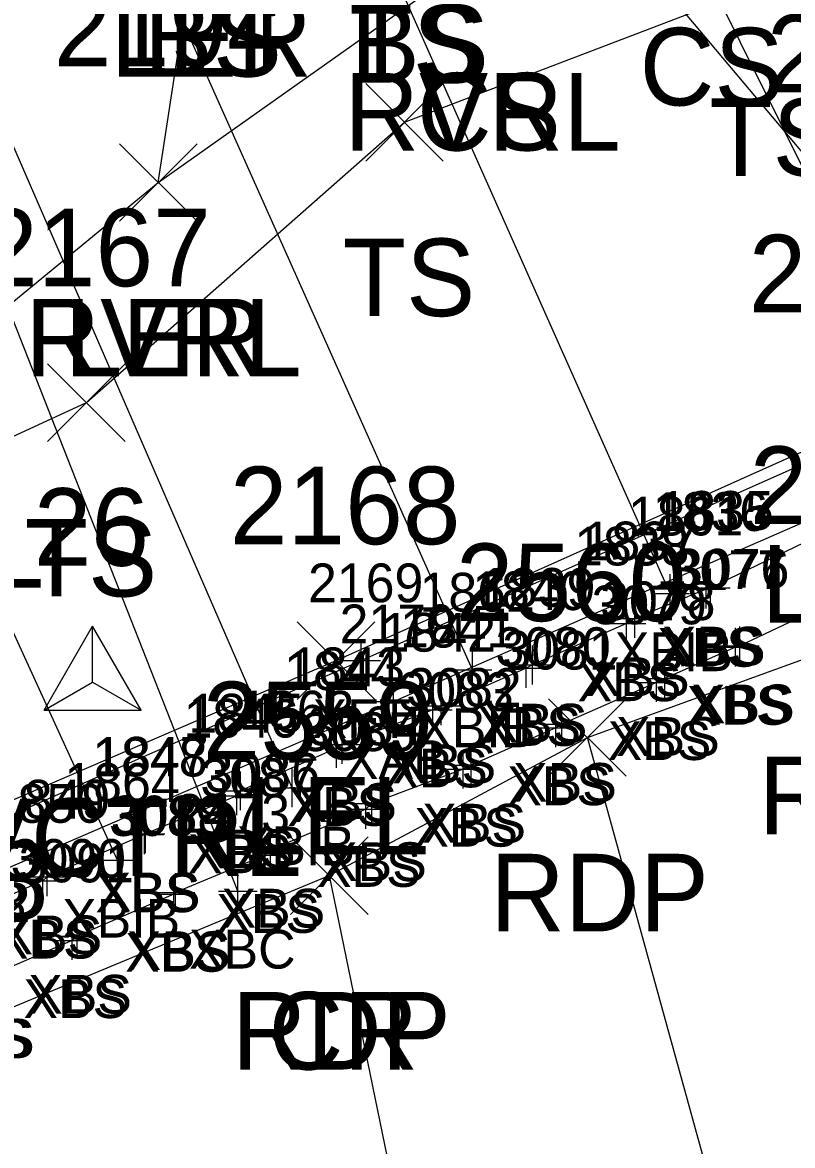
# Model space of a CAD drawing. Extents: x 1504228 to 1506103, y 437717 to 440106.
# Drawn here: x 1505221.56 to 1505241.43, y 438136.49 to 438165.45 of the extents above; entities that cross this region are included whole.
import ezdxf

# ---------------------------------------------------------------- set-up
doc = ezdxf.new("R2010")
doc.units = 0
for name, color, linetype in [('B_A', 7, 'Continuous'), ('B_I', 7, 'Continuous'), ('B_TIC', 7, 'Continuous'), ('BB', 7, 'Continuous'), ('BELB', 7, 'Continuous'), ('BFT', 7, 'Continuous'), ('BSE', 7, 'Continuous'), ('BSUBM', 7, 'Continuous'), ('C_A', 7, 'Continuous'), ('C_I', 7, 'Continuous'), ('CPSM', 7, 'Continuous'), ('L_A', 7, 'Continuous'), ('L_I', 7, 'Continuous'), ('L_TIC', 7, 'Continuous'), ('LARO', 7, 'Continuous'), ('LAWE', 7, 'Continuous'), ('LELB', 7, 'Continuous'), ('P_A', 7, 'Continuous'), ('P_I', 7, 'Continuous'), ('P_TIC', 7, 'Continuous'), ('PET', 7, 'Continuous'), ('PRC', 7, 'Continuous')]:
    doc.layers.add(name, color=color, linetype=linetype)

msp = doc.modelspace()

# ---------------------------------------------------------------- linework, layer by layer
at = {"layer": 'B_TIC'}
for p, q in [((1505238.275, 438150.725), (1505238.351, 438150.725)), ((1505239.203, 438150.84), (1505239.279, 438150.84)), ((1505239.321, 438150.871), (1505239.397, 438150.871)), ((1505237.363, 438150.082), (1505237.438, 438150.082)), ((1505237.147, 438149.952), (1505237.223, 438149.952)), ((1505239.962, 438149.343), (1505240.038, 438149.343)), ((1505240.074, 438149.38), (1505240.149, 438149.38)), ((1505230.306, 438149.002), (1505230.382, 438149.002)), ((1505233.18, 438148.763), (1505233.255, 438148.763)), ((1505234.558, 438148.799), (1505234.634, 438148.799)), ((1505234.723, 438148.885), (1505234.799, 438148.885)), ((1505237.922, 438148.434), (1505237.997, 438148.434)), ((1505238.14, 438148.54), (1505238.216, 438148.54)), ((1505231.138, 438147.944), (1505231.213, 438147.944)), ((1505232.371, 438147.836), (1505232.446, 438147.836)), ((1505232.155, 438147.729), (1505232.23, 438147.729)), ((1505235.331, 438147.268), (1505235.406, 438147.268)), ((1505235.483, 438147.357), (1505235.559, 438147.357)), ((1505229.663, 438146.737), (1505229.739, 438146.737)), ((1505229.809, 438146.837), (1505229.885, 438146.837)), ((1505233.14, 438146.305), (1505233.215, 438146.305)), ((1505232.933, 438146.201), (1505233.008, 438146.201)), ((1505228.526, 438145.721), (1505228.601, 438145.721)), ((1505227.095, 438145.514), (1505227.17, 438145.514)), ((1505227.192, 438145.642), (1505227.268, 438145.642)), ((1505230.422, 438145.164), (1505230.497, 438145.164)), ((1505230.581, 438145.312), (1505230.656, 438145.312)), ((1505224.712, 438144.511), (1505224.788, 438144.511)), ((1505224.739, 438144.531), (1505224.815, 438144.531)), ((1505227.824, 438143.977), (1505227.899, 438143.977)), ((1505227.96, 438144.114), (1505228.036, 438144.114)), ((1505224.017, 438143.855), (1505224.093, 438143.855)), ((1505222.205, 438143.424), (1505222.281, 438143.424)), ((1505222.086, 438143.316), (1505222.162, 438143.316)), ((1505225.471, 438142.975), (1505225.547, 438142.975)), ((1505225.514, 438143.016), (1505225.59, 438143.016)), ((1505227.125, 438143.057), (1505227.2, 438143.057)), ((1505222.849, 438141.78), (1505222.924, 438141.78)), ((1505222.972, 438141.895), (1505223.047, 438141.895))]:
    msp.add_line(p, q, dxfattribs=at)
for points in [[(1505238.272, 438150.225), (1505238.272, 438151.225)], [(1505239.2, 438150.34), (1505239.2, 438151.34)], [(1505239.318, 438150.371), (1505239.318, 438151.371)], [(1505237.772, 438150.725), (1505238.772, 438150.725)], [(1505238.7, 438150.84), (1505239.7, 438150.84)], [(1505238.818, 438150.871), (1505239.818, 438150.871)], [(1505237.144, 438149.452), (1505237.144, 438150.452)], [(1505237.359, 438149.582), (1505237.359, 438150.582)], [(1505236.859, 438150.082), (1505237.859, 438150.082)], [(1505236.644, 438149.952), (1505237.644, 438149.952)], [(1505239.959, 438148.843), (1505239.959, 438149.843)], [(1505240.07, 438148.88), (1505240.07, 438149.88)], [(1505230.303, 438148.502), (1505230.303, 438149.502)], [(1505233.176, 438148.263), (1505233.176, 438149.263)], [(1505234.555, 438148.299), (1505234.555, 438149.299)], [(1505234.72, 438148.385), (1505234.72, 438149.385)], [(1505239.459, 438149.343), (1505240.459, 438149.343)], [(1505239.57, 438149.38), (1505240.57, 438149.38)], [(1505229.803, 438149.002), (1505230.803, 438149.002)], [(1505237.918, 438147.934), (1505237.918, 438148.934)], [(1505238.137, 438148.04), (1505238.137, 438149.04)], [(1505232.676, 438148.763), (1505233.676, 438148.763)], [(1505234.055, 438148.799), (1505235.055, 438148.799)], [(1505234.22, 438148.885), (1505235.22, 438148.885)], [(1505231.134, 438147.444), (1505231.134, 438148.444)], [(1505232.367, 438147.336), (1505232.367, 438148.336)], [(1505237.418, 438148.434), (1505238.418, 438148.434)], [(1505237.637, 438148.54), (1505238.637, 438148.54)], [(1505232.151, 438147.229), (1505232.151, 438148.229)], [(1505230.634, 438147.944), (1505231.634, 438147.944)], [(1505231.867, 438147.836), (1505232.867, 438147.836)], [(1505235.327, 438146.768), (1505235.327, 438147.768)], [(1505235.48, 438146.857), (1505235.48, 438147.857)], [(1505231.651, 438147.729), (1505232.651, 438147.729)], [(1505229.66, 438146.237), (1505229.66, 438147.237)], [(1505229.806, 438146.337), (1505229.806, 438147.337)], [(1505234.827, 438147.268), (1505235.827, 438147.268)], [(1505234.98, 438147.357), (1505235.98, 438147.357)], [(1505229.16, 438146.737), (1505230.16, 438146.737)], [(1505229.306, 438146.837), (1505230.306, 438146.837)], [(1505232.929, 438145.701), (1505232.929, 438146.701)], [(1505233.136, 438145.805), (1505233.136, 438146.805)], [(1505232.636, 438146.305), (1505233.636, 438146.305)], [(1505227.091, 438145.014), (1505227.091, 438146.014)], [(1505227.189, 438145.142), (1505227.189, 438146.142)], [(1505228.522, 438145.221), (1505228.522, 438146.221)], [(1505232.429, 438146.201), (1505233.429, 438146.201)], [(1505228.022, 438145.721), (1505229.022, 438145.721)], [(1505230.577, 438144.812), (1505230.577, 438145.812)], [(1505226.591, 438145.514), (1505227.591, 438145.514)], [(1505226.689, 438145.642), (1505227.689, 438145.642)], [(1505230.418, 438144.664), (1505230.418, 438145.664)], [(1505229.918, 438145.164), (1505230.918, 438145.164)], [(1505230.077, 438145.312), (1505231.077, 438145.312)], [(1505224.709, 438144.011), (1505224.709, 438145.011)], [(1505224.736, 438144.031), (1505224.736, 438145.031)], [(1505227.957, 438143.614), (1505227.957, 438144.614)], [(1505224.014, 438143.355), (1505224.014, 438144.355)], [(1505224.209, 438144.511), (1505225.209, 438144.511)], [(1505224.236, 438144.531), (1505225.236, 438144.531)], [(1505227.82, 438143.477), (1505227.82, 438144.477)], [(1505227.32, 438143.977), (1505228.32, 438143.977)], [(1505227.457, 438144.114), (1505228.457, 438144.114)], [(1505222.083, 438142.816), (1505222.083, 438143.816)], [(1505222.202, 438142.924), (1505222.202, 438143.924)], [(1505223.514, 438143.855), (1505224.514, 438143.855)], [(1505221.702, 438143.424), (1505222.702, 438143.424)], [(1505225.468, 438142.475), (1505225.468, 438143.475)], [(1505225.511, 438142.516), (1505225.511, 438143.516)], [(1505227.121, 438142.557), (1505227.121, 438143.557)], [(1505221.583, 438143.316), (1505222.583, 438143.316)], [(1505224.968, 438142.975), (1505225.968, 438142.975)], [(1505225.011, 438143.016), (1505226.011, 438143.016)], [(1505226.621, 438143.057), (1505227.621, 438143.057)], [(1505222.846, 438141.28), (1505222.846, 438142.28)], [(1505222.968, 438141.395), (1505222.968, 438142.395)], [(1505222.346, 438141.78), (1505223.346, 438141.78)], [(1505222.468, 438141.895), (1505223.468, 438141.895)]]:
    msp.add_lwpolyline(points, dxfattribs=at)
at = {"layer": 'BB'}
for points in [[(1505245.599, 438153.876), (1505225.746, 438193.733)], [(1505238.272, 438150.725), (1505220.207, 438191.242)], [(1505233.176, 438148.763), (1505215.135, 438189.07)], [(1505228.522, 438145.721), (1505210.599, 438186.937)], [(1505224.014, 438143.855), (1505205.318, 438184.714)]]:
    msp.add_lwpolyline(points, dxfattribs=at)
at = {"layer": 'BELB'}
for points in [[(1505189.093, 438232.07), (1505202.074, 438213.317), (1505217.089, 438192.519), (1505234.002, 438171.224), (1505249.231, 438153.134)], [(1505227.121, 438143.057), (1505216.699, 438169.498), (1505208.631, 438188.54), (1505199.093, 438209.718)]]:
    msp.add_lwpolyline(points, dxfattribs=at)
at = {"layer": 'BFT'}
msp.add_lwpolyline([(1505211.711, 438138.978), (1505211.593, 438140.8), (1505215.376, 438142.417), (1505230.303, 438149.002), (1505243.278, 438154.766), (1505246.019, 438155.885), (1505263.291, 438163.511), (1505271.064, 438167.183), (1505276.649, 438169.866), (1505288.201, 438174.699), (1505288.73, 438173.49)], dxfattribs=at)
at = {"layer": 'BSE'}
for points in [[(1505242.683, 438152.495), (1505239.318, 438150.871), (1505239.2, 438150.84), (1505237.359, 438150.082), (1505237.144, 438149.952), (1505234.72, 438148.885), (1505234.555, 438148.799), (1505232.367, 438147.836), (1505232.151, 438147.729), (1505229.806, 438146.837), (1505229.66, 438146.737), (1505227.189, 438145.642), (1505227.091, 438145.514), (1505224.736, 438144.531), (1505224.709, 438144.511), (1505222.202, 438143.424), (1505222.083, 438143.316), (1505219.691, 438142.273), (1505219.626, 438142.286), (1505217.345, 438141.296)], [(1505243.419, 438150.958), (1505240.07, 438149.38), (1505239.959, 438149.343), (1505238.137, 438148.54), (1505237.918, 438148.434), (1505235.48, 438147.357), (1505235.327, 438147.268), (1505233.136, 438146.305), (1505232.929, 438146.201), (1505230.577, 438145.312), (1505230.418, 438145.164), (1505227.957, 438144.114), (1505227.82, 438143.977), (1505225.511, 438143.016), (1505225.468, 438142.975), (1505222.968, 438141.895), (1505222.846, 438141.78), (1505220.458, 438140.756), (1505220.355, 438140.756), (1505218.11, 438139.776)]]:
    msp.add_lwpolyline(points, dxfattribs=at)
at = {"layer": 'BSUBM'}
msp.add_lwpolyline([(1505214.761, 438127.389), (1505213.65, 438134.809), (1505212.657, 438139.975), (1505231.134, 438147.944), (1505243.637, 438153.412), (1505246.753, 438154.837), (1505263.932, 438162.477), (1505271.425, 438165.886), (1505277.465, 438168.561), (1505287.974, 438173.167), (1505291.052, 438171.05), (1505297.268, 438166.649), (1505302.136, 438162.984), (1505307.468, 438159.403), (1505307.306, 438158.962)], dxfattribs=at)
at = {"layer": 'CPSM'}
for p, q in [((1505222.122, 438147.721), (1505223.372, 438149.886)), ((1505224.622, 438147.721), (1505223.372, 438149.886)), ((1505223.372, 438148.442), (1505223.372, 438149.886)), ((1505222.122, 438147.721), (1505223.372, 438148.442)), ((1505223.372, 438148.442), (1505223.372, 438148.442)), ((1505223.372, 438148.442), (1505224.622, 438147.721)), ((1505222.122, 438147.721), (1505224.622, 438147.721))]:
    msp.add_line(p, q, dxfattribs=at)
at = {"layer": 'L_TIC'}
for points in [[(1505230.417, 438161.88), (1505232.417, 438163.88)], [(1505232.417, 438161.88), (1505230.417, 438163.88)], [(1505224.066, 438160.326), (1505226.066, 438162.326)], [(1505226.066, 438160.326), (1505224.066, 438162.326)], [(1505224.066, 438160.326), (1505226.066, 438162.326)], [(1505226.066, 438160.326), (1505224.066, 438162.326)], [(1505222.21, 438154.651), (1505224.21, 438156.651)], [(1505224.21, 438154.651), (1505222.21, 438156.651)], [(1505228.653, 438147.999), (1505230.653, 438149.999)], [(1505230.653, 438147.999), (1505228.653, 438149.999)]]:
    msp.add_lwpolyline(points, dxfattribs=at)
at = {"layer": 'LARO'}
for points in [[(1505225.066, 438161.326), (1505226.248, 438169.057), (1505228.34, 438173.672), (1505225.288, 438173.876), (1505239.482, 438178.474), (1505243.528, 438176.585), (1505251.729, 438176.792), (1505258.116, 438181.066), (1505273.159, 438181.503), (1505274.516, 438179.171), (1505287.419, 438180.921)], [(1505211.067, 438140.867), (1505215.631, 438142.954), (1505229.653, 438148.999), (1505242.992, 438154.978), (1505245.889, 438156.33), (1505263.257, 438163.856), (1505270.634, 438167.43), (1505277.265, 438170.598), (1505281.289, 438172.305), (1505281.518, 438175.58), (1505285.106, 438180.489), (1505287.419, 438180.921)]]:
    msp.add_lwpolyline(points, dxfattribs=at)
at = {"layer": 'LAWE'}
msp.add_lwpolyline([(1505191.715, 438146.002), (1505202.906, 438148.803), (1505214.791, 438151.569), (1505218.42, 438155.881), (1505225.066, 438161.326), (1505233.297, 438167.151), (1505239.085, 438170.522), (1505246.461, 438173.024), (1505251.729, 438176.792), (1505260.319, 438178.7), (1505267.708, 438179.756), (1505273.159, 438181.503), (1505280.716, 438184.584), (1505293.606, 438188.67), (1505306.287, 438194.997), (1505316.183, 438195.439), (1505329.815, 438205.572), (1505347.823, 438213.433)], dxfattribs=at)
at = {"layer": 'LELB'}
msp.add_lwpolyline([(1505215.631, 438142.954), (1505216.782, 438152.684), (1505223.21, 438155.651), (1505231.417, 438162.88), (1505240.87, 438166.496), (1505250.977, 438169.557), (1505260.591, 438172.084), (1505271.035, 438170.915), (1505277.265, 438170.598), (1505281.518, 438175.58), (1505287.828, 438178.641), (1505292.056, 438179.708), (1505296.753, 438181.832), (1505306.221, 438188.545)], dxfattribs=at)
at = {"layer": 'P_TIC'}
for points in [[(1505235.137, 438146.016), (1505237.137, 438148.016)], [(1505237.137, 438146.016), (1505235.137, 438148.016)], [(1505235.137, 438146.016), (1505237.137, 438148.016)], [(1505237.137, 438146.016), (1505235.137, 438148.016)], [(1505228.478, 438142.453), (1505230.478, 438144.453)], [(1505230.478, 438142.453), (1505228.478, 438144.453)], [(1505228.478, 438142.453), (1505230.478, 438144.453)], [(1505230.478, 438142.453), (1505228.478, 438144.453)]]:
    msp.add_lwpolyline(points, dxfattribs=at)
at = {"layer": 'PET'}
for points in [[(1505219.541, 438139.332), (1505229.478, 438143.453), (1505236.137, 438147.016), (1505243.065, 438149.521), (1505252.019, 438153.342), (1505263.781, 438158.664), (1505277.038, 438164.677), (1505295.889, 438147.093), (1505311.676, 438134.175), (1505338.301, 438109.134), (1505363.246, 438092.977), (1505381.83, 438081.07), (1505419.293, 438061.963), (1505441.952, 438049.929), (1505474.016, 438032.73)], [(1505244.336, 438117.338), (1505236.137, 438147.016)]]:
    msp.add_lwpolyline(points, dxfattribs=at)
at = {"layer": 'PRC'}
msp.add_lwpolyline([(1505229.478, 438143.453), (1505234.695, 438118.095), (1505243.623, 438084.856), (1505253.152, 438053.473), (1505260.454, 438023.846), (1505266.195, 437991.874), (1505273.558, 437955.361), (1505281.379, 437913.196)], dxfattribs=at)

# ---------------------------------------------------------------- texts
at = {"layer": 'B_A'}
for s, p in [('XBS', (1505237.94, 438148.84)), ('XBS', (1505238.058, 438148.871)), ('XBIB', (1505236.843, 438148.725)), ('XBS', (1505235.884, 438147.952)), ('XBS', (1505236.099, 438148.082)), ('XBS', (1505238.699, 438147.343)), ('XBS', (1505238.81, 438147.38)), ('XFT', (1505229.047, 438147.002)), ('XBIB', (1505231.747, 438146.763)), ('XBS', (1505233.295, 438146.799)), ('XBS', (1505233.46, 438146.885)), ('XBS', (1505236.877, 438146.54)), ('XBS', (1505236.659, 438146.434)), ('XAB', (1505229.855, 438145.944)), ('XBS', (1505230.891, 438145.729)), ('XBS', (1505231.107, 438145.836)), ('XBS', (1505234.22, 438145.357)), ('XBS', (1505234.068, 438145.268)), ('XBS', (1505228.4, 438144.737)), ('XBS', (1505228.546, 438144.837)), ('XBS', (1505231.67, 438144.201)), ('XBS', (1505231.877, 438144.305)), ('XBS', (1505225.929, 438143.642)), ('XBIB', (1505227.093, 438143.721)), ('XBS', (1505225.831, 438143.514)), ('XBS', (1505229.317, 438143.312)), ('XBS', (1505229.159, 438143.164)), ('XBS', (1505223.449, 438142.511)), ('XBS', (1505223.476, 438142.531)), ('XBS', (1505226.697, 438142.114)), ('XBIB', (1505222.584, 438141.855)), ('XBS', (1505226.561, 438141.977)), ('XBS', (1505220.823, 438141.316)), ('XBS', (1505220.942, 438141.424)), ('XBS', (1505224.208, 438140.975)), ('XBS', (1505224.251, 438141.016)), ('XBC', (1505225.857, 438141.057)), ('XBS', (1505221.586, 438139.78)), ('XBS', (1505221.708, 438139.895)), ('XBS', (1505219.095, 438138.756)), ('XBS', (1505219.198, 438138.756))]:
    msp.add_text(s, height=1, dxfattribs=at).set_placement(p)
at = {"layer": 'B_I'}
for s, p in [('1836', (1505237.826, 438152.34)), ('1835', (1505237.971, 438152.371)), ('1861', (1505237.185, 438152.225)), ('1838', (1505235.797, 438151.452)), ('1837', (1505236.013, 438151.582)), ('3077', (1505238.29, 438150.843)), ('3076', (1505238.373, 438150.88)), ('2169', (1505228.929, 438150.502)), ('1862', (1505231.806, 438150.263)), ('1840', (1505233.165, 438150.299)), ('1839', (1505233.369, 438150.385)), ('3079', (1505236.245, 438149.934)), ('3078', (1505236.468, 438150.04)), ('2170', (1505229.744, 438149.444)), ('1841', (1505231.304, 438149.336)), ('1842', (1505230.805, 438149.229)), ('3080', (1505233.767, 438148.857)), ('3081', (1505233.942, 438148.768)), ('1844', (1505228.313, 438148.237)), ('1843', (1505228.459, 438148.337)), ('3083', (1505231.26, 438147.701)), ('3082', (1505231.467, 438147.805)), ('1845', (1505225.842, 438147.142)), ('1863', (1505227.152, 438147.221)), ('1846', (1505225.717, 438147.014)), ('3084', (1505228.908, 438146.812)), ('3085', (1505228.749, 438146.664)), ('1848', (1505223.362, 438146.011)), ('1847', (1505223.389, 438146.031)), ('3086', (1505226.26, 438145.614)), ('1864', (1505222.643, 438145.355)), ('3087', (1505226.151, 438145.477)), ('1850', (1505220.693, 438144.816)), ('1849', (1505220.852, 438144.924)), ('3089', (1505223.794, 438144.475)), ('3088', (1505223.842, 438144.516)), ('2473', (1505225.491, 438144.557)), ('3090', (1505221.256, 438143.395)), ('3091', (1505221.46, 438143.28)), ('3093', (1505218.686, 438142.256)), ('3092', (1505218.789, 438142.256))]:
    msp.add_text(s, height=1, dxfattribs=at).set_placement(p)
at = {"layer": 'C_A'}
msp.add_text('HVCTRL', height=2, dxfattribs=at).set_placement((1505218.065, 438143.442))
at = {"layer": 'C_I'}
msp.add_text('26', height=2, dxfattribs=at).set_placement((1505221.853, 438151.442))
at = {"layer": 'L_A'}
for s, p in [('LER', (1505223.831, 438164.057)), ('BS', (1505224.689, 438164.057)), ('TS', (1505229.997, 438163.903)), ('BS', (1505230.028, 438163.903)), ('CS', (1505237.484, 438163.314)), ('RVRL', (1505229.864, 438162.151)), ('CS', (1505231.738, 438162.151)), ('TS', (1505239.28, 438161.496)), ('TS', (1505229.826, 438157.88)), ('RVRL', (1505221.633, 438156.326)), ('LER', (1505222.649, 438156.326)), ('RVRL', (1505214.987, 438150.881)), ('TS', (1505221.62, 438150.651)), ('LEL', (1505240.63, 438149.978)), ('LEL', (1505227.291, 438143.999))]:
    msp.add_text(s, height=2, dxfattribs=at).set_placement(p)
at = {"layer": 'L_I'}
for s, p in [('2194', (1505222.373, 438164.326)), ('2194', (1505222.373, 438164.326)), ('2179', (1505240.767, 438163.651)), ('2167', (1505220.47, 438158.651)), ('2173', (1505240.299, 438157.978)), ('2168', (1505226.913, 438151.999))]:
    msp.add_text(s, height=2, dxfattribs=at).set_placement(p)
at = {"layer": 'P_A'}
for s, p in [('RDP', (1505240.553, 438144.521)), ('RDP', (1505240.553, 438144.521)), ('RDP', (1505233.625, 438142.016)), ('RDP', (1505233.625, 438142.016)), ('RDP', (1505226.966, 438138.453)), ('CR', (1505227.911, 438138.453))]:
    msp.add_text(s, height=2, dxfattribs=at).set_placement(p)
at = {"layer": 'P_I'}
for s, p in [('2561', (1505240.325, 438152.521)), ('2561', (1505240.325, 438152.521)), ('2560', (1505232.744, 438150.016)), ('2560', (1505232.744, 438150.016)), ('2559', (1505226.21, 438146.453)), ('2559', (1505226.21, 438146.453)), ('2558', (1505216.281, 438142.332)), ('2558', (1505216.281, 438142.332))]:
    msp.add_text(s, height=2, dxfattribs=at).set_placement(p)

doc.saveas('drawing.dxf')
